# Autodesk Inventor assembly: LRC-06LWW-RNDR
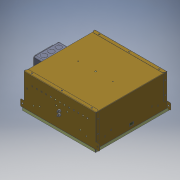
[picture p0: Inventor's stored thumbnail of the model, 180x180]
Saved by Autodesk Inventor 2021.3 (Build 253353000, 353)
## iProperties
load_classification: Lighting
motor: 0 ul
Part Number: LRC-06LWW-RNDR
Document SubType Name: Assembly
Designer: JChurch
description: 0:0:Lensed 6" Wall Wash - COB LED
manufacturer: 0:0:The Kirlin Company
model: 0:0:LRC-06LWW
url: 0:0:
Author: JChurch
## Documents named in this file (6)
- X:\Revit Files\0000-Un-Zipped\COB\LRC-06LWW-RND\LRC-06LWW-RNDR.iam
- X:\INVENTOR\830\830399-00-00.ipt
- X:\INVENTOR\881\881088-00-00.iam
- X:\INVENTOR\700\700458-00-XX.iam
- X:\INVENTOR\KIRLIN_ENG\725\725075-02-00.ipt
- X:\Revit Files\0000-Un-Zipped\COB\LRC-06LWW-RND\LRC-06LWW-RNDR_Substitute_1.ipt
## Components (5 placed, 5 different names)
1. 830399-00-00:1 — Mate:1, Mate:2, Mate:3, Mate:4, Tangent:1, Angle:1, Insert:1, Mate:5
2. 881088-00-00:1 [sub-assembly] — Mate:4, Tangent:1, Angle:1
3. 700458-00-XX:1 [sub-assembly] — Insert:1, Mate:5, Mate:6, Mate:7
4. 725075-02-00:1 — Mate:6, Mate:7
5. LRC-06LWW-RNDR_Substitute_1:1
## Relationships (10: Mate 7, Tangent 1, Angle 1, Insert 1)
- Mate:1: 830399-00-00:1
- Mate:2: 830399-00-00:1
- Mate:3: 830399-00-00:1
- Mate:4: 830399-00-00:1 ↔ 881088-00-00:1
- Tangent:1: 830399-00-00:1 ↔ 881088-00-00:1
- Angle:1: 830399-00-00:1 ↔ 881088-00-00:1
- Insert:1: 830399-00-00:1 ↔ 700458-00-XX:1
- Mate:5: 830399-00-00:1 ↔ 700458-00-XX:1
- Mate:6: 700458-00-XX:1 ↔ 725075-02-00:1
- Mate:7: 700458-00-XX:1 ↔ 725075-02-00:1
